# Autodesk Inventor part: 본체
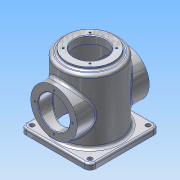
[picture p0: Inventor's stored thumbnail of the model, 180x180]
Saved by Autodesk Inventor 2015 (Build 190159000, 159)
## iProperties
Created: 2015-10
Part Number: 본체
Material: Aluminum 6061
Document SubType Name: Modeling
Designer: 602-22
Density: 2.7 g/cm^3
Appearance: Aluminum - Flat
Mass: 982.357 g
Surface Area: 1037.38 cm^2
Volume: 363.836 cm^3
Author: 602-22
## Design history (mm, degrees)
sketch "Sketch1"
  geometry: L1 (60, -60)-(-60, -60); L2 (-60, -60)-(-60, 60); L3 (-60, 60)-(60, 60); L4 (60, 60)-(60, -60); L5 (0, -60)-(0, 60); 2 further points
  constraints: 10 end point, 3 midpoint, 2 parallel, 1 coincident, 1 horizontal, 1 perpendicular
  dimensions: "d0" = 120 distance of L2.end L3.end; "d1" = 120 distance of L1.end L2.end
extrude "Extrusion1" new body sketch "Sketch1" distance "d2" = 10; taper "d3" = 0 deg
sketch "Sketch2"
  geometry: C1 r 50 at (0, 0); 1 further point
  constraints: 1 centre point, 1 coincident
  dimensions: "d4" = 100 diameter of C1
extrude "Extrusion2" join sketch "Sketch2" distance "d5" = 110; taper "d6" = 0 deg
workplane "Work Plane1"
sketch "Sketch4"
  geometry: L1 (60, 0)-(60, 60); C1 r 40 at (60, 60)
  constraints: 2 end point, 1 centre point, 1 coincident, 1 vertical
  dimensions: "d15" = 60 distance of L1.start L1.end; "d16" = 80 diameter of C1
extrude "Extrusion3" join sketch "Sketch4" stored distance "d17" = 124; taper "d18" = 0 deg
sketch "Sketch5"
  geometry: C1 r 40 at (0, 0) reference; C2 r 27 at (0, 0); 1 further point
  constraints: 1 centre point, 1 coincident
  dimensions: "d19" = 54 diameter of C2
extrude "Extrusion4" cut sketch "Sketch5" stored distance "d20" = 124; taper "d21" = 0 deg
workplane "Work Plane2"
sketch "Sketch6"
  geometry: C1 r 40 at (0, 0); 1 further point
  constraints: 1 centre point, 1 coincident
  dimensions: "d23" = 80 diameter of C1
extrude "Extrusion5" join sketch "Sketch6" stored distance "d24" = 124; taper "d25" = 0 deg
sketch "Sketch7"
  geometry: C1 r 27 at (0, 0); 1 further point
  constraints: 1 centre point, 1 coincident
  dimensions: "d26" = 54 diameter of C1
extrude "Extrusion6" cut sketch "Sketch7" distance "d27" = 13; taper "d28" = 0 deg
sketch "Sketch8"
  geometry: C1 r 45 at (0, 0); 1 further point
  constraints: 1 centre point, 1 coincident
  dimensions: "d29" = 90 diameter of C1
extrude "Extrusion7" cut sketch "Sketch8" distance "d30" = 112; taper "d31" = 0 deg
chamfer "Chamfer2" distance "d35" = 1; stored, may be unused: second distance "d36" = 2, angle "d37" = 45 deg
chamfer "Chamfer3" distance "d38" = 3; stored, may be unused: second distance "d39" = 2, angle "d40" = 45 deg
fillet "Fillet1" dims "d41" = 10, "d42" = 5, "d70" = 3
sketch "Sketch9"
  geometry: L1 (22.981, -22.981)-(-22.981, 22.981); L2 (22.981, 22.981)-(-22.981, -22.981); L3 (0, 0)-(32.5, 0); A1 r 32.5 centre (0, 0) between (22.981, -22.981) and (-22.981, 22.981); 1 further point
  constraints: 6 end point, 5 point on circle, 2 coincident, 2 midpoint, 1 centre point, 1 horizontal
  dimensions: "d44" = 65 diameter of A1; "d45" = 45 deg angle of L3 L2; "d46" = 90 deg angle of L1 L2
hole "Hole1" sketch "Sketch9" at (-22.981, 22.981), (22.981, 22.981), (-22.981, -22.981), (22.981, -22.981) diameter "d47" = 3.242; stored, may be unused: countersink angle "d51" = 90 deg, drill point angle "d53" = 118 deg; dims "d48" = 8, "d49" = 4, "d50" = 2, "d52" = 10
sketch "Sketch10"
  geometry: L1 (0, 32.5)-(0, -32.5); L2 (-32.5, 0)-(32.5, 0); C1 r 28 at (0, 0) reference; A1 r 32.5 centre (0, 0) between (-32.5, 0) and (0, 32.5); 2 further points
  constraints: 4 end point, 4 point on circle, 2 coincident, 2 midpoint, 1 centre point, 1 horizontal, 1 vertical
  dimensions: "d54" = 65 diameter of A1
hole "Hole2" sketch "Sketch10" at (0, 32.5), (0, -32.5), (32.5, 0), (-32.5, 0) diameter "d55" = 3.242; stored, may be unused: countersink angle "d59" = 90 deg, drill point angle "d61" = 118 deg; dims "d56" = 8, "d57" = 4, "d58" = 2, "d60" = 10
sketch "Sketch11"
  geometry: L1 (0, 32.5)-(0, -32.5); L2 (32.5, 0)-(-32.5, 0); C1 r 28 at (0, 0) reference; A1 r 32.5 centre (0, 0) between (0, 32.5) and (0, -32.5); 2 further points
  constraints: 4 end point, 4 point on circle, 2 coincident, 2 midpoint, 1 centre point, 1 horizontal, 1 vertical
  dimensions: "d62" = 65 diameter of A1
hole "Hole3" sketch "Sketch11" at (0, 32.5), (32.5, 0), (0, -32.5), (-32.5, 0) diameter "d63" = 3.242; stored, may be unused: countersink angle "d67" = 90 deg, drill point angle "d69" = 118 deg; dims "d64" = 8, "d65" = 4, "d66" = 2, "d68" = 10
sketch "Sketch12"
  geometry: L1 (-50, 50)-(50, 50); L2 (50, 50)-(50, -50); L3 (50, -50)-(-50, -50); L4 (-50, -50)-(-50, 50); L5 (0, 50)-(0, -50); 2 further points
  constraints: 10 end point, 3 midpoint, 2 parallel, 1 coincident, 1 horizontal, 1 perpendicular
  dimensions: "d71" = 100 distance of L2.end L3.end; "d72" = 100 distance of L1.end L2.end
hole "Hole4" sketch "Sketch12" at (-50, 50), (50, 50), (50, -50), (-50, -50) diameter "d73" = 8; stored, may be unused: countersink angle "d77" = 90 deg, drill point angle "d79" = 118 deg; dims "d74" = 8, "d75" = 4, "d76" = 2, "d78" = 10
workplane "Work Plane7"
  workplane "Work Plane6"
sketch "Sketch18"
  geometry: L1 (50, 0)-(50, 70); 1 further point
  constraints: 2 end point, 1 coincident, 1 vertical, 1 other
  dimensions: "d84" = 70 distance of L1.start L1.end
emboss "Emboss1" sketch "Sketch18" dims "d0" = 120, "d1" = 120, "d85" = 0.5, "d86" = 0
body "Solid1"
other parameters: "d22" = 5, "d83" = 50.5
